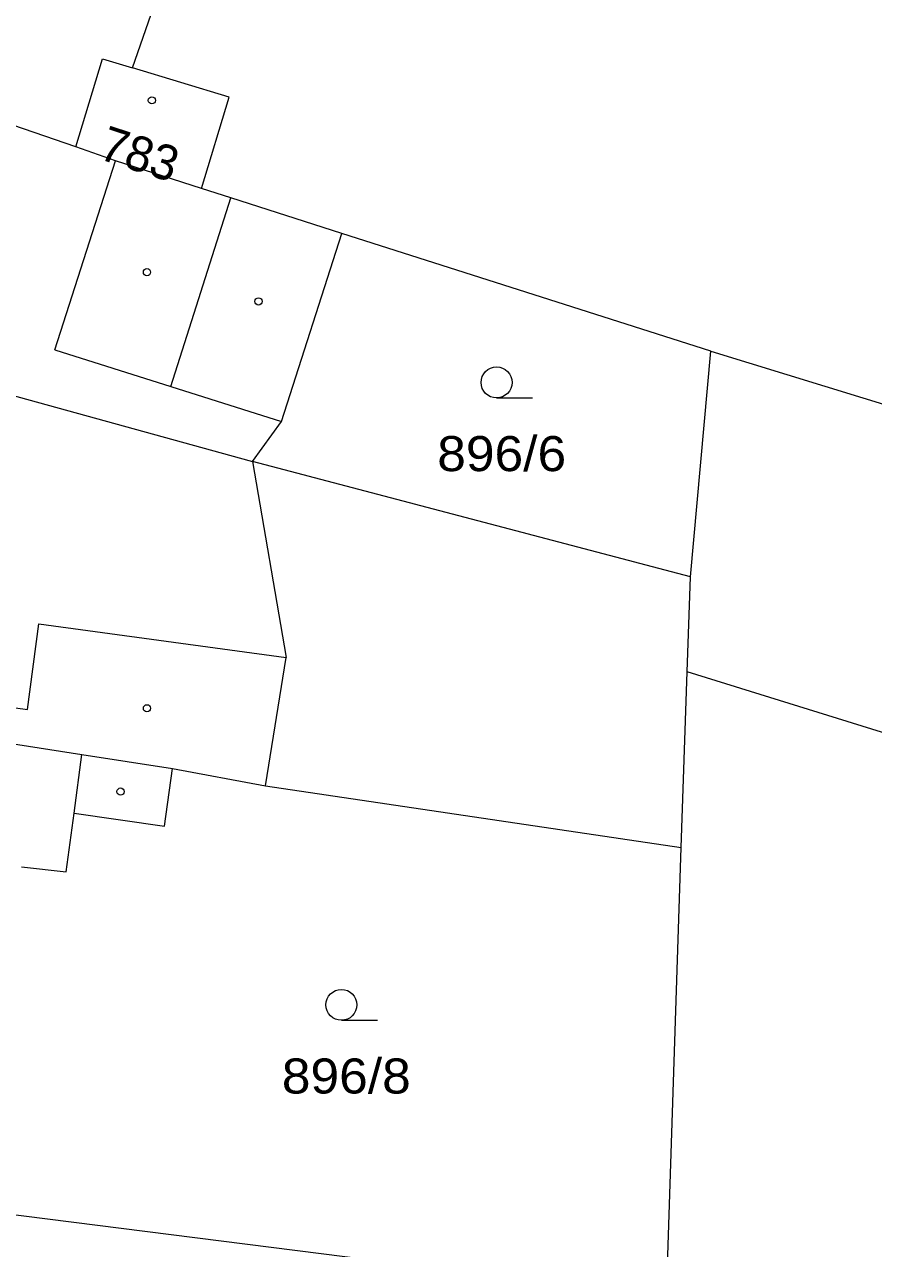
# Model space of a CAD drawing. Extents: x -686207 to -681951, y -1020493 to -1017811.
# Drawn here: x -682474.5 to -682433.3, y -1019130.3 to -1019070.9 of the extents above; entities that cross this region are included whole.
import ezdxf

# ---------------------------------------------------------------- set-up
doc = ezdxf.new("R2010")
doc.units = 0
doc.header["$LTSCALE"] = 0.4
for name, color, linetype, lineweight in [('1', 7, 'Continuous', 13), ('3', 7, 'Continuous', 13), ('4', 7, 'Continuous', 13), ('5', 7, 'Continuous', 13)]:
    doc.layers.add(name, color=color, linetype=linetype, lineweight=lineweight)
doc.layers.add('2', color=7, linetype='Continuous')

msp = doc.modelspace()

# ---------------------------------------------------------------- linework, layer by layer
at = {"layer": '1'}
for p, q in [((-682441.15, -1019086.78), (-682459.06, -1019081.08)), ((-682494.02, -1019083.7), (-682463.4, -1019092.14)), ((-682442.14, -1019097.72), (-682441.15, -1019086.78)), ((-682441.15, -1019086.78), (-682398.25, -1019099.97)), ((-682442.14, -1019097.72), (-682463.4, -1019092.14)), ((-682442.3, -1019102.33), (-682442.14, -1019097.72)), ((-682398.73, -1019115.87), (-682442.3, -1019102.33)), ((-682443.31, -1019132.66), (-682442.6, -1019110.85)), ((-682443.31, -1019132.66), (-682476.03, -1019128.54))]:
    msp.add_line(p, q, dxfattribs=at)
for points in [[(-682469.22, -1019073.05), (-682465.5, -1019062.34), (-682465.52, -1019059.75)], [(-682471.97, -1019076.88), (-682476.55, -1019075.3), (-682490.47, -1019071.19)], [(-682471.97, -1019076.88), (-682470.68, -1019072.61), (-682469.22, -1019073.05)], [(-682465.87, -1019078.89), (-682464.53, -1019074.47), (-682469.22, -1019073.05)], [(-682465.87, -1019078.89), (-682470.05, -1019077.55), (-682471.97, -1019076.88)], [(-682459.06, -1019081.08), (-682464.44, -1019079.35), (-682465.87, -1019078.89)], [(-682463.4, -1019092.14), (-682461.99, -1019090.2), (-682459.06, -1019081.08)], [(-682467.28, -1019107.02), (-682462.77, -1019107.86), (-682442.6, -1019110.85), (-682442.3, -1019102.33)], [(-682484.23, -1019104.39), (-682478.94, -1019105.21), (-682471.67, -1019106.34), (-682467.28, -1019107.02)], [(-682474.6, -1019111.78), (-682472.44, -1019112.03), (-682472.05, -1019109.19), (-682467.67, -1019109.81), (-682467.28, -1019107.02)]]:
    msp.add_lwpolyline(points, dxfattribs=at)
at = {"layer": '3'}
for p, q in [((-682451.553, -1019089.05), (-682449.803, -1019089.05)), ((-682459.083, -1019119.23), (-682457.333, -1019119.23))]:
    msp.add_line(p, q, dxfattribs=at)
for centre in [(-682451.5529, -1019088.2998), (-682459.0829, -1019118.4798)]:
    msp.add_circle(centre, 0.75, dxfattribs=at)
at = {"layer": '4'}
for p, q in [((-682472.98, -1019086.71), (-682470.05, -1019077.55)), ((-682467.36, -1019088.5), (-682464.44, -1019079.35)), ((-682472.98, -1019086.71), (-682467.36, -1019088.5)), ((-682467.36, -1019088.5), (-682461.99, -1019090.2)), ((-682463.4, -1019092.14), (-682461.76, -1019101.64)), ((-682474.32, -1019104.16), (-682473.76, -1019100.01)), ((-682473.76, -1019100.01), (-682461.76, -1019101.64)), ((-682462.77, -1019107.86), (-682461.76, -1019101.64)), ((-682472.05, -1019109.19), (-682471.67, -1019106.34))]:
    msp.add_line(p, q, dxfattribs=at)
msp.add_lwpolyline([(-682478.94, -1019105.21), (-682478.77, -1019103.55), (-682474.32, -1019104.16)], dxfattribs=at)
at = {"layer": '5'}
for centre in [(-682468.2768, -1019074.6192), (-682468.5168, -1019082.9492), (-682463.1068, -1019084.3692), (-682468.5168, -1019104.0992), (-682469.7968, -1019108.1392)]:
    msp.add_circle(centre, 0.175, dxfattribs=at)

# ---------------------------------------------------------------- texts
at = {"layer": '2'}
msp.add_text('783', height=1.7, rotation=342, dxfattribs=at).set_placement((-682470.93, -1019077.438))
at = {"layer": '2', "width": 1.1}
for s, p in [('896/6', (-682454.433, -1019092.6)), ('896/8', (-682461.973, -1019122.78))]:
    msp.add_text(s, height=1.7, dxfattribs=at).set_placement(p)

doc.saveas('drawing.dxf')
